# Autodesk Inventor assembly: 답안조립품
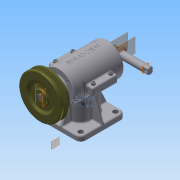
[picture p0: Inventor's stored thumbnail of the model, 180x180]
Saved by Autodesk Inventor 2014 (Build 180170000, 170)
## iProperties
Created: 2015-05
Part Number: 답안조립품
Document SubType Name: Assembly
Designer: net
Author: net
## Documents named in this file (18)
- C:\Users\net\Desktop\350507V1037\답안조립품.iam
- C:\Users\net\Desktop\350507V1037\본체.ipt
- C:\Users\net\Desktop\350507V1037\본체 커버.ipt
- C:\Users\net\Desktop\350507V1037\뒤커버.ipt
- C:\Users\net\Desktop\350507V1037\베어링 6202.ipt
- C:\Users\net\Desktop\350507V1037\앞커버.ipt
- C:\Users\net\Desktop\350507V1037\베어링 6201.ipt
- C:\Users\net\Desktop\350507V1037\오일실.ipt
- C:\Users\net\Desktop\350507V1037\편심축.ipt
- C:\Users\net\Desktop\350507V1037\키4x4.ipt
- C:\Users\net\Desktop\350507V1037\V-벨트풀리.ipt
- C:\Users\net\Desktop\350507V1037\멈춤나사.ipt
- C:\Users\net\Desktop\350507V1037\링크.ipt
- C:\Users\net\Desktop\350507V1037\너트 M8.ipt
- C:\Users\net\Desktop\350507V1037\M4x0.5x14.ipt
- C:\Users\net\Desktop\350507V1037\M3x0.5x8.ipt
- C:\Users\net\Desktop\350507V1037\슬라이드.ipt
- C:\Users\net\Desktop\350507V1037\가변스프링.ipt
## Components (15 placed, 5 different names)
1. V-벨트풀리:1
2. KS B 1012 C - 미터 C M8:1
3. M4x0.5x14:1
4. M4x0.5x14:2
5. M4x0.5x14:3
6. M4x0.5x14:4
7. M3x0.5x8:1
8. M3x0.5x8:2
9. M3x0.5x8:3
10. M3x0.5x8:4
11. M3x0.5x8:5
12. M3x0.5x8:6
13. M3x0.5x8:7
14. M3x0.5x8:8
15. 가변스프링:1
